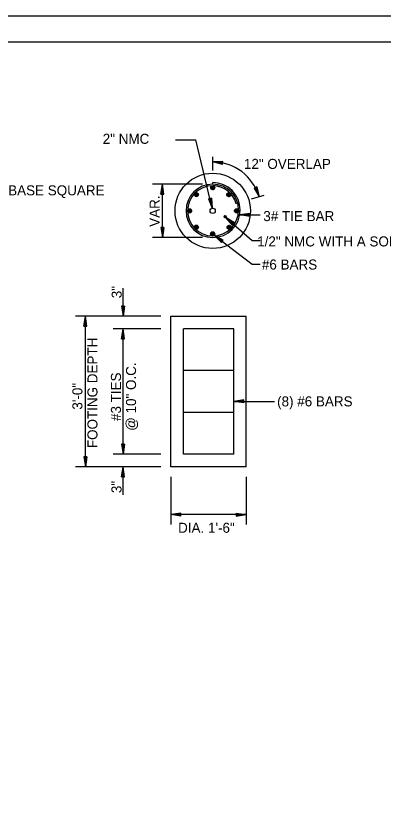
# Model space of a CAD drawing. Extents: x 1369885 to 1370886, y 379976 to 380616.
# Drawn here: x 1370434.9 to 1370599.4, y 380262.3 to 380615.6 of the extents above; entities that cross this region are included whole.
import ezdxf

# ---------------------------------------------------------------- set-up
doc = ezdxf.new("R2010")
doc.units = 0
for name, color, linetype in [('R_Border', 7, 'Continuous'), ('R_Draft', 7, 'Continuous'), ('R_No Plot', 7, 'Continuous')]:
    doc.layers.add(name, color=color, linetype=linetype)

msp = doc.modelspace()

# ---------------------------------------------------------------- linework, layer by layer
at = {"layer": 'R_Border'}
msp.add_line((1369922.71, 380603.9), (1370871.25, 380603.9), dxfattribs=at)
at = {"layer": 'R_Draft'}
for p, q in [((1370506.33, 380559.94), (1370515.54, 380559.94)), ((1370522.77, 380529.32), (1370515.54, 380559.94)), ((1370523.03, 380546.18), (1370523.03, 380552.34)), ((1370527.59, 380550.28), (1370523.04, 380550.18)), ((1370527.42, 380548.94), (1370523.04, 380550.18)), ((1370527.58, 380550.17), (1370523.79, 380550.09)), ((1370527.43, 380549.05), (1370523.79, 380550.09)), ((1370527.56, 380550.05), (1370524.55, 380549.99)), ((1370527.45, 380549.17), (1370524.55, 380549.99)), ((1370527.55, 380549.94), (1370525.3, 380549.89)), ((1370527.46, 380549.28), (1370525.3, 380549.89)), ((1370527.53, 380549.83), (1370526.05, 380549.8)), ((1370527.48, 380549.39), (1370526.05, 380549.8)), ((1370527.52, 380549.71), (1370526.8, 380549.7)), ((1370527.49, 380549.5), (1370526.8, 380549.7)), ((1370527.42, 380548.94), (1370527.59, 380550.28)), ((1370518.53, 380540.13), (1370496.03, 380540.13)), ((1370499.86, 380535.63), (1370500.53, 380540.13)), ((1370499.97, 380535.63), (1370500.53, 380539.38)), ((1370500.09, 380535.63), (1370500.53, 380538.61)), ((1370500.53, 380516.22), (1370500.53, 380540.13)), ((1370501.21, 380535.63), (1370500.53, 380540.13)), ((1370501.1, 380535.63), (1370500.53, 380539.38)), ((1370500.98, 380535.63), (1370500.53, 380538.61)), ((1370522.14, 380538.49), (1370523.07, 380539.42)), ((1370522.14, 380538.65), (1370522.91, 380539.42)), ((1370522.15, 380538.34), (1370523.22, 380539.41)), ((1370522.19, 380538.22), (1370523.34, 380539.37)), ((1370522.2, 380538.87), (1370522.69, 380539.36)), ((1370522.24, 380538.11), (1370523.45, 380539.32)), ((1370522.3, 380538.01), (1370523.55, 380539.26)), ((1370522.37, 380537.92), (1370523.64, 380539.19)), ((1370522.45, 380537.84), (1370523.72, 380539.11)), ((1370522.54, 380537.77), (1370523.79, 380539.02)), ((1370522.64, 380537.72), (1370523.84, 380538.92)), ((1370522.75, 380537.67), (1370523.89, 380538.81)), ((1370522.88, 380537.64), (1370523.92, 380538.68)), ((1370523.03, 380540.13), (1370523.03, 380540.84)), ((1370542.79, 380538.88), (1370541.53, 380538.39)), ((1370541.95, 380538.56), (1370542.68, 380537.27)), ((1370542.06, 380538.6), (1370542.41, 380537.97)), ((1370542.26, 380538.67), (1370542.41, 380537.97)), ((1370542.36, 380538.71), (1370542.68, 380537.27)), ((1370542.47, 380538.75), (1370542.95, 380536.56)), ((1370542.58, 380538.79), (1370543.22, 380535.86)), ((1370542.68, 380538.84), (1370543.5, 380535.13)), ((1370542.79, 380538.88), (1370543.77, 380534.43)), ((1370499.86, 380535.63), (1370501.21, 380535.63)), ((1370500.2, 380535.63), (1370500.53, 380537.86)), ((1370500.32, 380535.63), (1370500.53, 380537.09)), ((1370500.43, 380535.63), (1370500.53, 380536.34)), ((1370500.87, 380535.63), (1370500.53, 380537.86)), ((1370500.75, 380535.63), (1370500.53, 380537.09)), ((1370500.64, 380535.63), (1370500.53, 380536.34)), ((1370514.82, 380535.38), (1370515.83, 380536.39)), ((1370514.82, 380535.53), (1370515.68, 380536.39)), ((1370514.84, 380535.72), (1370515.49, 380536.37)), ((1370514.85, 380535.25), (1370515.96, 380536.36)), ((1370514.89, 380535.13), (1370516.08, 380536.32)), ((1370514.95, 380535.03), (1370516.18, 380536.26)), ((1370514.99, 380536.02), (1370515.19, 380536.22)), ((1370515.01, 380534.93), (1370516.28, 380536.2)), ((1370515.09, 380534.85), (1370516.36, 380536.12)), ((1370515.17, 380534.78), (1370516.43, 380536.04)), ((1370515.27, 380534.71), (1370516.5, 380535.94)), ((1370515.38, 380534.66), (1370516.55, 380535.83)), ((1370515.5, 380534.62), (1370516.59, 380535.71)), ((1370515.63, 380534.6), (1370516.61, 380535.58)), ((1370515.79, 380534.6), (1370516.61, 380535.42)), ((1370515.99, 380534.64), (1370516.57, 380535.22)), ((1370523.03, 380537.63), (1370523.93, 380538.53)), ((1370523.2, 380537.64), (1370523.92, 380538.36)), ((1370523.44, 380537.72), (1370523.84, 380538.12)), ((1370529.35, 380535.31), (1370530.33, 380536.29)), ((1370529.35, 380535.47), (1370530.17, 380536.29)), ((1370529.38, 380535.17), (1370530.47, 380536.27)), ((1370529.39, 380535.67), (1370529.98, 380536.25)), ((1370529.42, 380535.05), (1370530.59, 380536.23)), ((1370529.47, 380534.95), (1370530.7, 380536.17)), ((1370529.53, 380534.85), (1370530.79, 380536.11)), ((1370529.61, 380534.77), (1370530.88, 380536.04)), ((1370529.69, 380534.69), (1370530.95, 380535.95)), ((1370529.78, 380534.62), (1370531.02, 380535.86)), ((1370529.89, 380534.57), (1370531.07, 380535.76)), ((1370530, 380534.53), (1370531.12, 380535.64)), ((1370530.14, 380534.5), (1370531.14, 380535.51)), ((1370530.29, 380534.49), (1370531.15, 380535.36)), ((1370530.47, 380534.52), (1370531.12, 380535.17)), ((1370545.92, 380535.08), (1370540.27, 380533.38)), ((1370541.53, 380538.39), (1370543.77, 380534.43)), ((1370541.63, 380538.43), (1370543.5, 380535.13)), ((1370541.74, 380538.47), (1370543.22, 380535.86)), ((1370541.84, 380538.51), (1370542.95, 380536.56)), ((1370522.42, 380533.85), (1370521.1, 380533.55)), ((1370521.1, 380533.55), (1370522.77, 380529.32)), ((1370521.21, 380533.58), (1370522.6, 380530.05)), ((1370521.32, 380533.6), (1370522.42, 380530.8)), ((1370521.43, 380533.63), (1370522.26, 380531.53)), ((1370521.55, 380533.65), (1370522.09, 380532.28)), ((1370521.66, 380533.68), (1370521.92, 380533.01)), ((1370521.86, 380533.73), (1370521.92, 380533.01)), ((1370521.97, 380533.75), (1370522.09, 380532.28)), ((1370522.09, 380533.78), (1370522.26, 380531.53)), ((1370522.2, 380533.8), (1370522.42, 380530.8)), ((1370522.31, 380533.83), (1370522.6, 380530.05)), ((1370522.42, 380533.85), (1370522.77, 380529.32)), ((1370530.77, 380534.66), (1370530.99, 380534.87)), ((1370534.23, 380531.56), (1370533.56, 380531.35)), ((1370511.79, 380528.07), (1370512.79, 380529.07)), ((1370511.79, 380528.22), (1370512.64, 380529.07)), ((1370511.81, 380528.41), (1370512.45, 380529.04)), ((1370511.82, 380527.93), (1370512.93, 380529.04)), ((1370511.86, 380527.82), (1370513.04, 380529)), ((1370511.91, 380527.71), (1370513.15, 380528.95)), ((1370511.97, 380528.72), (1370512.14, 380528.89)), ((1370511.98, 380527.62), (1370513.24, 380528.88)), ((1370512.05, 380527.53), (1370513.33, 380528.81)), ((1370512.14, 380527.46), (1370513.4, 380528.72)), ((1370512.23, 380527.4), (1370513.46, 380528.63)), ((1370512.34, 380527.34), (1370513.52, 380528.52)), ((1370512.46, 380527.3), (1370513.56, 380528.4)), ((1370512.6, 380527.28), (1370513.58, 380528.26)), ((1370512.75, 380527.28), (1370513.58, 380528.11)), ((1370532.79, 380528.19), (1370533.68, 380529.08)), ((1370532.8, 380528.04), (1370533.83, 380529.07)), ((1370532.81, 380528.37), (1370533.5, 380529.05)), ((1370532.83, 380527.91), (1370533.96, 380529.04)), ((1370532.88, 380527.79), (1370534.07, 380528.99)), ((1370532.91, 380528.63), (1370533.24, 380528.95)), ((1370532.93, 380527.69), (1370534.18, 380528.93)), ((1370533, 380527.6), (1370534.27, 380528.87)), ((1370533.08, 380527.52), (1370534.35, 380528.79)), ((1370533.17, 380527.45), (1370534.42, 380528.7)), ((1370533.26, 380527.38), (1370534.48, 380528.61)), ((1370533.37, 380527.33), (1370534.53, 380528.5)), ((1370533.5, 380527.3), (1370534.57, 380528.37)), ((1370533.63, 380527.28), (1370534.59, 380528.24)), ((1370533.8, 380527.28), (1370534.59, 380528.07)), ((1370512.95, 380527.32), (1370513.54, 380527.91)), ((1370528.11, 380525.55), (1370528.58, 380526.02)), ((1370528.13, 380525.42), (1370528.71, 380526)), ((1370528.16, 380525.77), (1370528.36, 380525.97)), ((1370528.18, 380525.31), (1370528.82, 380525.95)), ((1370528.25, 380525.22), (1370528.91, 380525.88)), ((1370528.34, 380525.15), (1370528.98, 380525.79)), ((1370528.45, 380525.1), (1370529.03, 380525.68)), ((1370528.59, 380525.08), (1370529.05, 380525.54)), ((1370528.81, 380525.15), (1370528.98, 380525.32)), ((1370528.91, 380525.21), (1370540.74, 380514.88)), ((1370531.88, 380521.76), (1370528.91, 380525.21)), ((1370532.76, 380522.78), (1370528.91, 380525.21)), ((1370531.95, 380521.84), (1370529.48, 380524.72)), ((1370532.68, 380522.69), (1370529.48, 380524.72)), ((1370534.01, 380527.33), (1370534.54, 380527.86)), ((1370539.64, 380527), (1370535.14, 380526.33)), ((1370535.14, 380526.33), (1370544.35, 380526.33)), ((1370539.64, 380525.65), (1370535.14, 380526.33)), ((1370539.64, 380526.89), (1370535.89, 380526.33)), ((1370539.64, 380525.76), (1370535.89, 380526.33)), ((1370539.64, 380526.77), (1370536.67, 380526.33)), ((1370539.64, 380525.88), (1370536.67, 380526.33)), ((1370539.64, 380526.66), (1370537.42, 380526.33)), ((1370539.64, 380525.99), (1370537.42, 380526.33)), ((1370539.64, 380526.55), (1370538.18, 380526.33)), ((1370539.64, 380526.11), (1370538.18, 380526.33)), ((1370539.64, 380526.43), (1370538.93, 380526.33)), ((1370539.64, 380526.22), (1370538.93, 380526.33)), ((1370539.64, 380525.65), (1370539.64, 380527)), ((1370514.82, 380520.77), (1370515.8, 380521.75)), ((1370514.82, 380520.93), (1370515.64, 380521.75)), ((1370514.84, 380520.64), (1370515.93, 380521.73)), ((1370514.86, 380521.13), (1370515.44, 380521.71)), ((1370514.88, 380520.52), (1370516.05, 380521.69)), ((1370514.93, 380520.41), (1370516.16, 380521.64)), ((1370515, 380520.31), (1370516.26, 380521.58)), ((1370515.07, 380520.23), (1370516.34, 380521.5)), ((1370515.15, 380520.15), (1370516.42, 380521.42)), ((1370515.25, 380520.09), (1370516.48, 380521.32)), ((1370515.35, 380520.03), (1370516.54, 380521.22)), ((1370515.47, 380519.99), (1370516.58, 380521.1)), ((1370515.6, 380519.96), (1370516.61, 380520.97)), ((1370529.5, 380520.7), (1370530.51, 380521.71)), ((1370529.5, 380520.86), (1370530.35, 380521.71)), ((1370529.53, 380520.57), (1370530.64, 380521.68)), ((1370529.53, 380521.04), (1370530.17, 380521.68)), ((1370529.57, 380520.45), (1370530.76, 380521.64)), ((1370529.63, 380520.35), (1370530.86, 380521.58)), ((1370529.68, 380521.35), (1370529.86, 380521.53)), ((1370529.69, 380520.25), (1370530.96, 380521.52)), ((1370529.77, 380520.17), (1370531.04, 380521.44)), ((1370529.85, 380520.1), (1370531.11, 380521.36)), ((1370529.95, 380520.03), (1370531.18, 380521.26)), ((1370530.05, 380519.98), (1370531.23, 380521.16)), ((1370532.61, 380522.61), (1370530.07, 380524.21)), ((1370532.02, 380521.93), (1370530.07, 380524.21)), ((1370530.17, 380519.94), (1370531.27, 380521.04)), ((1370530.31, 380519.92), (1370531.29, 380520.9)), ((1370532.1, 380522.01), (1370530.63, 380523.72)), ((1370532.54, 380522.52), (1370530.63, 380523.72)), ((1370532.46, 380522.44), (1370531.21, 380523.22)), ((1370532.17, 380522.1), (1370531.21, 380523.22)), ((1370532.39, 380522.35), (1370531.78, 380522.73)), ((1370532.25, 380522.19), (1370531.78, 380522.73)), ((1370531.88, 380521.76), (1370532.76, 380522.78)), ((1370499.86, 380520.72), (1370500.53, 380516.22)), ((1370501.21, 380520.72), (1370499.86, 380520.72)), ((1370499.97, 380520.72), (1370500.53, 380516.97)), ((1370500.09, 380520.72), (1370500.53, 380517.75)), ((1370500.2, 380520.72), (1370500.53, 380518.5)), ((1370500.31, 380520.72), (1370500.53, 380519.26)), ((1370500.43, 380520.72), (1370500.53, 380520.01)), ((1370501.21, 380520.72), (1370500.53, 380516.22)), ((1370500.75, 380520.72), (1370500.53, 380519.26)), ((1370500.98, 380520.72), (1370500.53, 380517.75)), ((1370501.1, 380520.72), (1370500.53, 380516.97)), ((1370500.87, 380520.72), (1370500.53, 380518.5)), ((1370500.64, 380520.72), (1370500.53, 380520.01)), ((1370515.75, 380519.96), (1370516.61, 380520.82)), ((1370515.94, 380519.99), (1370516.59, 380520.63)), ((1370516.24, 380520.12), (1370516.45, 380520.33)), ((1370522.1, 380517.78), (1370523.12, 380518.8)), ((1370522.1, 380517.93), (1370522.96, 380518.8)), ((1370522.12, 380517.64), (1370523.26, 380518.77)), ((1370522.14, 380518.13), (1370522.77, 380518.76)), ((1370522.16, 380517.52), (1370523.38, 380518.74)), ((1370522.21, 380517.41), (1370523.49, 380518.68)), ((1370522.27, 380517.31), (1370523.58, 380518.62)), ((1370522.34, 380518.49), (1370522.4, 380518.56)), ((1370522.35, 380517.23), (1370523.67, 380518.55)), ((1370522.43, 380517.15), (1370523.75, 380518.47)), ((1370522.52, 380517.08), (1370523.82, 380518.38)), ((1370522.62, 380517.02), (1370523.87, 380518.28)), ((1370522.73, 380516.98), (1370523.92, 380518.17)), ((1370522.86, 380516.94), (1370523.95, 380518.04)), ((1370523, 380516.93), (1370523.97, 380517.9)), ((1370523.17, 380516.94), (1370523.96, 380517.73)), ((1370523.39, 380516.99), (1370523.9, 380517.51)), ((1370530.47, 380519.92), (1370531.29, 380520.74)), ((1370530.66, 380519.95), (1370531.26, 380520.55)), ((1370518.53, 380516.22), (1370496.03, 380516.22)), ((1370523.71, 380517.21), (1370540.74, 380504.32)), ((1370526.9, 380513.96), (1370523.71, 380517.21)), ((1370527.71, 380515.04), (1370523.71, 380517.21)), ((1370526.96, 380514.05), (1370524.31, 380516.75)), ((1370527.64, 380514.95), (1370524.31, 380516.75)), ((1370527.57, 380514.86), (1370524.93, 380516.29)), ((1370527.03, 380514.14), (1370524.93, 380516.29)), ((1370527.1, 380514.23), (1370525.52, 380515.84)), ((1370527.5, 380514.77), (1370525.52, 380515.84)), ((1370527.43, 380514.68), (1370526.13, 380515.38)), ((1370527.17, 380514.33), (1370526.13, 380515.38)), ((1370527.37, 380514.58), (1370526.73, 380514.93)), ((1370527.24, 380514.41), (1370526.73, 380514.93)), ((1370526.9, 380513.96), (1370527.71, 380515.04)), ((1370540.74, 380514.88), (1370544.35, 380514.88)), ((1370540.74, 380504.32), (1370544.35, 380504.32)), ((1370482.93, 380480.97), (1370482.93, 380493.48)), ((1370482.26, 380485.47), (1370482.93, 380480.97)), ((1370483.61, 380485.47), (1370482.26, 380485.47)), ((1370482.37, 380485.47), (1370482.93, 380481.73)), ((1370482.48, 380485.47), (1370482.93, 380482.5)), ((1370482.6, 380485.47), (1370482.93, 380483.25)), ((1370482.71, 380485.47), (1370482.93, 380484.01)), ((1370482.83, 380485.47), (1370482.93, 380484.76)), ((1370483.61, 380485.47), (1370482.93, 380480.97)), ((1370483.15, 380485.47), (1370482.93, 380484.01)), ((1370483.38, 380485.47), (1370482.93, 380482.5)), ((1370483.5, 380485.47), (1370482.93, 380481.73)), ((1370483.27, 380485.47), (1370482.93, 380483.25)), ((1370483.04, 380485.47), (1370482.93, 380484.76)), ((1370499.81, 380480.97), (1370461.56, 380480.97)), ((1370465.38, 380476.47), (1370466.06, 380480.97)), ((1370465.5, 380476.47), (1370466.06, 380480.22)), ((1370465.61, 380476.47), (1370466.06, 380479.45)), ((1370465.72, 380476.47), (1370466.06, 380478.7)), ((1370466.06, 380413.47), (1370466.06, 380480.97)), ((1370466.73, 380476.47), (1370466.06, 380480.97)), ((1370466.62, 380476.47), (1370466.06, 380480.22)), ((1370466.51, 380476.47), (1370466.06, 380479.45)), ((1370466.39, 380476.47), (1370466.06, 380478.7)), ((1370504.31, 380413.47), (1370504.31, 380480.97)), ((1370504.31, 380480.97), (1370538.06, 380480.97)), ((1370538.06, 380413.47), (1370538.06, 380480.97)), ((1370465.38, 380476.47), (1370466.73, 380476.47)), ((1370465.84, 380476.47), (1370466.06, 380477.94)), ((1370465.95, 380476.47), (1370466.06, 380477.19)), ((1370466.28, 380476.47), (1370466.06, 380477.94)), ((1370466.16, 380476.47), (1370466.06, 380477.19)), ((1370499.81, 380475.35), (1370478.43, 380475.35)), ((1370482.26, 380470.85), (1370482.93, 380475.35)), ((1370482.93, 380419.1), (1370482.93, 380475.35)), ((1370483.61, 380470.85), (1370482.93, 380475.35)), ((1370532.43, 380475.35), (1370509.93, 380475.35)), ((1370509.93, 380419.1), (1370509.93, 380475.35)), ((1370532.43, 380419.1), (1370532.43, 380475.35)), ((1370482.37, 380470.85), (1370482.93, 380474.6)), ((1370482.48, 380470.85), (1370482.93, 380473.82)), ((1370482.6, 380470.85), (1370482.93, 380473.07)), ((1370482.71, 380470.85), (1370482.93, 380472.31)), ((1370482.83, 380470.85), (1370482.93, 380471.56)), ((1370483.5, 380470.85), (1370482.93, 380474.6)), ((1370483.38, 380470.85), (1370482.93, 380473.82)), ((1370483.27, 380470.85), (1370482.93, 380473.07)), ((1370483.15, 380470.85), (1370482.93, 380472.31)), ((1370483.04, 380470.85), (1370482.93, 380471.56)), ((1370482.26, 380470.85), (1370483.61, 380470.85)), ((1370532.43, 380456.6), (1370509.93, 380456.6)), ((1370536.94, 380443.46), (1370532.44, 380442.78)), ((1370536.94, 380443.35), (1370533.19, 380442.78)), ((1370536.94, 380443.23), (1370533.97, 380442.78)), ((1370536.94, 380442.11), (1370536.94, 380443.46)), ((1370536.94, 380442.11), (1370532.44, 380442.78)), ((1370532.44, 380442.78), (1370550.77, 380442.78)), ((1370536.94, 380442.22), (1370533.19, 380442.78)), ((1370536.94, 380442.34), (1370533.97, 380442.78)), ((1370536.94, 380443.12), (1370534.72, 380442.78)), ((1370536.94, 380442.45), (1370534.72, 380442.78)), ((1370536.94, 380443), (1370535.48, 380442.78)), ((1370536.94, 380442.56), (1370535.48, 380442.78)), ((1370536.94, 380442.89), (1370536.23, 380442.78)), ((1370536.94, 380442.68), (1370536.23, 380442.78)), ((1370532.43, 380437.85), (1370509.93, 380437.85)), ((1370482.26, 380423.6), (1370482.93, 380419.1)), ((1370483.61, 380423.6), (1370482.26, 380423.6)), ((1370482.37, 380423.6), (1370482.93, 380419.85)), ((1370482.48, 380423.6), (1370482.93, 380420.63)), ((1370482.6, 380423.6), (1370482.93, 380421.37)), ((1370482.71, 380423.6), (1370482.93, 380422.14)), ((1370482.83, 380423.6), (1370482.93, 380422.89)), ((1370483.61, 380423.6), (1370482.93, 380419.1)), ((1370483.15, 380423.6), (1370482.93, 380422.14)), ((1370483.38, 380423.6), (1370482.93, 380420.63)), ((1370483.5, 380423.6), (1370482.93, 380419.85)), ((1370483.27, 380423.6), (1370482.93, 380421.37)), ((1370483.04, 380423.6), (1370482.93, 380422.89)), ((1370499.81, 380419.1), (1370478.43, 380419.1)), ((1370532.43, 380419.1), (1370509.93, 380419.1)), ((1370465.38, 380417.97), (1370466.06, 380413.47)), ((1370466.73, 380417.97), (1370465.38, 380417.97)), ((1370465.5, 380417.97), (1370466.06, 380414.23)), ((1370465.61, 380417.97), (1370466.06, 380415)), ((1370465.72, 380417.97), (1370466.06, 380415.75)), ((1370465.84, 380417.97), (1370466.06, 380416.51)), ((1370465.95, 380417.97), (1370466.06, 380417.26)), ((1370466.73, 380417.97), (1370466.06, 380413.47)), ((1370466.28, 380417.97), (1370466.06, 380416.51)), ((1370466.51, 380417.97), (1370466.06, 380415)), ((1370466.62, 380417.97), (1370466.06, 380414.23)), ((1370466.39, 380417.97), (1370466.06, 380415.75)), ((1370466.16, 380417.97), (1370466.06, 380417.26)), ((1370499.81, 380413.47), (1370461.56, 380413.47)), ((1370482.26, 380408.97), (1370482.93, 380413.47)), ((1370482.37, 380408.97), (1370482.93, 380412.72)), ((1370482.48, 380408.97), (1370482.93, 380411.95)), ((1370482.93, 380400.97), (1370482.93, 380413.47)), ((1370483.61, 380408.97), (1370482.93, 380413.47)), ((1370483.5, 380408.97), (1370482.93, 380412.72)), ((1370483.38, 380408.97), (1370482.93, 380411.95)), ((1370538.06, 380413.47), (1370504.31, 380413.47)), ((1370482.26, 380408.97), (1370483.61, 380408.97)), ((1370482.6, 380408.97), (1370482.93, 380411.2)), ((1370482.71, 380408.97), (1370482.93, 380410.44)), ((1370482.83, 380408.97), (1370482.93, 380409.69)), ((1370483.27, 380408.97), (1370482.93, 380411.2)), ((1370483.15, 380408.97), (1370482.93, 380410.44)), ((1370483.04, 380408.97), (1370482.93, 380409.69)), ((1370504.31, 380408.97), (1370504.31, 380387.6)), ((1370538.06, 380408.97), (1370538.06, 380387.6)), ((1370508.81, 380392.77), (1370504.31, 380392.1)), ((1370538.06, 380392.1), (1370504.31, 380392.1)), ((1370508.81, 380391.42), (1370504.31, 380392.1)), ((1370508.81, 380392.66), (1370505.06, 380392.1)), ((1370508.81, 380391.54), (1370505.06, 380392.1)), ((1370508.81, 380392.55), (1370505.83, 380392.1)), ((1370508.81, 380391.65), (1370505.83, 380392.1)), ((1370508.81, 380392.43), (1370506.58, 380392.1)), ((1370508.81, 380391.76), (1370506.58, 380392.1)), ((1370508.81, 380392.32), (1370507.35, 380392.1)), ((1370508.81, 380391.88), (1370507.35, 380392.1)), ((1370508.81, 380392.21), (1370508.1, 380392.1)), ((1370508.81, 380391.99), (1370508.1, 380392.1)), ((1370508.81, 380391.42), (1370508.81, 380392.77)), ((1370533.56, 380392.77), (1370538.06, 380392.1)), ((1370533.56, 380392.77), (1370533.56, 380391.42)), ((1370533.56, 380392.66), (1370537.31, 380392.1)), ((1370533.56, 380392.55), (1370536.53, 380392.1)), ((1370533.56, 380392.43), (1370535.78, 380392.1)), ((1370533.56, 380392.32), (1370535.02, 380392.1)), ((1370533.56, 380392.21), (1370534.27, 380392.1)), ((1370533.56, 380391.42), (1370538.06, 380392.1)), ((1370533.56, 380391.88), (1370535.02, 380392.1)), ((1370533.56, 380391.65), (1370536.53, 380392.1)), ((1370533.56, 380391.54), (1370537.31, 380392.1)), ((1370533.56, 380391.76), (1370535.78, 380392.1)), ((1370533.56, 380391.99), (1370534.27, 380392.1))]:
    msp.add_line(p, q, dxfattribs=at)
for centre, radius in [((1370523.03, 380528.18), 16.87), ((1370523.03, 380538.53), 0.9), ((1370515.72, 380535.49), 0.9), ((1370530.25, 380535.39), 0.9), ((1370512.68, 380528.18), 0.9), ((1370523.03, 380528.18), 1.17), ((1370533.69, 380528.18), 0.9), ((1370528.58, 380525.55), 0.469), ((1370515.72, 380520.86), 0.9), ((1370530.4, 380520.81), 0.9), ((1370523.03, 380517.86), 0.937)]:
    msp.add_circle(centre, radius, dxfattribs=at)
for centre, radius, start, end in [((1370523.03, 380528.53), 21.56, 15.8939, 90), ((1370523.03, 380528.18), 11.95, 90, 270), ((1370523.03, 380528.18), 11.25, 90, 270), ((1370523.03, 380528.53), 12.31, 270, 90), ((1370523.03, 380528.53), 11.6, 270, 90), ((1370523.03, 380528.53), 10.9, 43.6894, 90), ((1370523.03, 380528.53), 10.9, 15.0162, 90)]:
    msp.add_arc(centre, radius, start, end, dxfattribs=at)
at = {"layer": 'R_No Plot'}
msp.add_line((1369885.51, 380615.59), (1370885.51, 380615.59), dxfattribs=at)
msp.add_lwpolyline([(1369885.49, 380615.59), (1370885.51, 380615.59), (1370885.51, 379975.58), (1369885.49, 379975.58)], close=True, dxfattribs=at)

# ---------------------------------------------------------------- texts
at = {"layer": 'R_Draft'}
for s, p in [('2" NMC', (1370473.79, 380558.2)), ('12" OVERLAP', (1370537.01, 380546.96)), ('ANCHOR BASE SQUARE', (1370403.7, 380535.11)), ('3# TIE BAR', (1370545.69, 380523.57)), (' 1/2" NMC WITH A SOLID 1C/#8 A.W.G., E.G.C.', (1370541.27, 380512.22)), ('#6 BARS', (1370545.06, 380501.87)), ('(8) #6 BARS', (1370551.87, 380440.54)), ('DIA. 1\'-6"', (1370507.54, 380383.9))]:
    msp.add_text(s, height=4.5, dxfattribs=at).set_placement(p)
for s, p in [('VAR.', (1370499.26, 380521.02)), ('3"', (1370482.27, 380489.01)), ('FOOTING DEPTH', (1370471.44, 380421.85)), ('@ 10" O.C.', (1370488.71, 380429.61)), ('#3 TIES', (1370481.96, 380434)), ('3\'-0"', (1370464.69, 380439.09)), ('3"', (1370482.2, 380401.69))]:
    msp.add_text(s, height=4.5, rotation=90, dxfattribs=at).set_placement(p)

doc.saveas('drawing.dxf')
